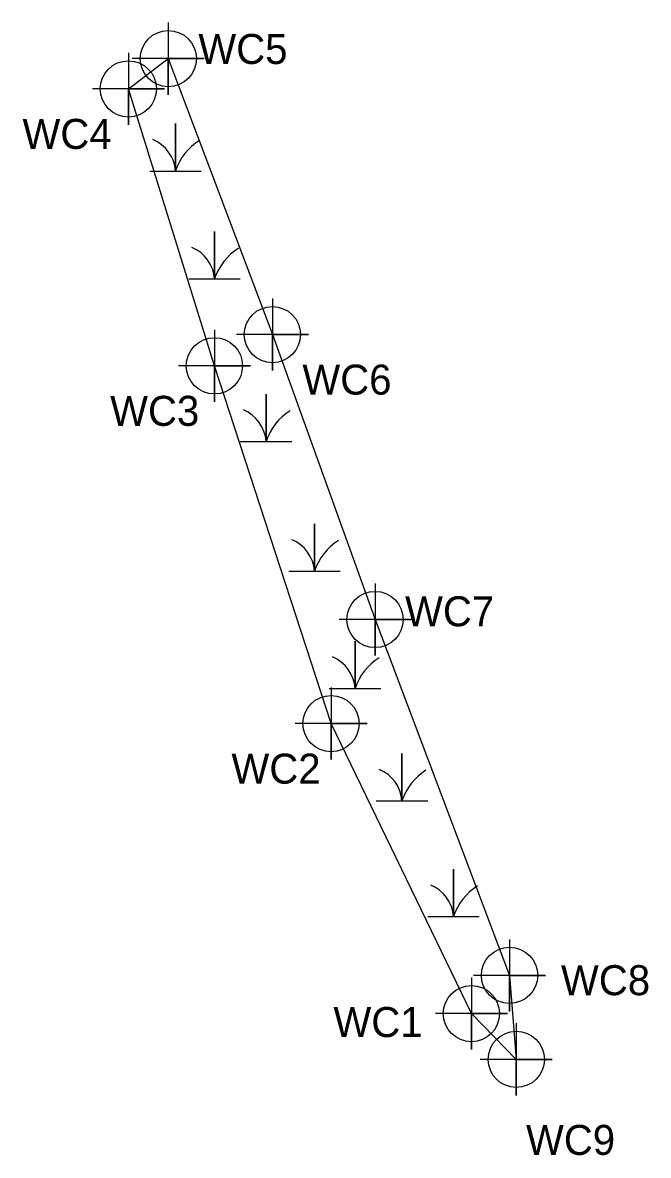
# Model space of a CAD drawing. Extents: x 2603618 to 2605510, y 618189 to 619022.
# Drawn here: x 2603693.4 to 2603745.5, y 618592.9 to 618687.3 of the extents above; entities that cross this region are included whole.
import ezdxf

# ---------------------------------------------------------------- set-up
doc = ezdxf.new("R2010")
doc.units = 0
for name, color, linetype in [('Exist Environmental Wetland Boundary', 7, 'Continuous'), ('Exist Environmental Wetland Boundary Cogo Comment', 7, 'Continuous'), ('Exist Environmental Wetland Boundary Cogo Point CELL', 7, 'Continuous'), ('Exist Hydro Swamp or Marsh', 7, 'Continuous')]:
    doc.layers.add(name, color=color, linetype=linetype)

# ---------------------------------------------------------------- blocks, each defined once
blk = doc.blocks.new('Exist Hydro Swamp or Marsh')
at = {"layer": 'Exist Hydro Swamp or Marsh'}
blk.add_line((0, 0), (0, 0), dxfattribs=at)
blk.add_lwpolyline([(-0.043, -0.0357), (0, -0.0357), (0, 0.0432), (0, -0.0357), (0.043, -0.0357)], dxfattribs=at)
for centre, radius, start, end in [((-0.0613, -0.0401), 0.0615, 4.1403, 67.535), ((0.0912, -0.066), 0.0961, 122.1274, 161.6222)]:
    blk.add_arc(centre, radius, start, end, dxfattribs=at)

msp = doc.modelspace()

# ---------------------------------------------------------------- linework, layer by layer
at = {"layer": 'Exist Environmental Wetland Boundary'}
msp.add_line((2603730.792, 618604.745), (2603734.534, 618600.938), dxfattribs=at)
msp.add_lwpolyline([(2603730.792, 618604.745), (2603719.096, 618628.908), (2603709.376, 618658.718), (2603702.202, 618681.791), (2603705.534, 618684.31), (2603714.205, 618661.32), (2603722.762, 618637.586), (2603733.971, 618607.934), (2603734.534, 618600.938)], dxfattribs=at)
at = {"layer": 'Exist Environmental Wetland Boundary Cogo Point CELL'}
for points in [[(2603705.534, 618687.31), (2603705.534, 618681.31), (2603705.534, 618684.31), (2603708.534, 618684.31), (2603702.534, 618684.31)], [(2603702.202, 618684.791), (2603702.202, 618678.791), (2603702.202, 618681.791), (2603705.202, 618681.791), (2603699.202, 618681.791)], [(2603714.205, 618664.32), (2603714.205, 618658.32), (2603714.205, 618661.32), (2603717.205, 618661.32), (2603711.205, 618661.32)], [(2603709.376, 618661.718), (2603709.376, 618655.718), (2603709.376, 618658.718), (2603712.376, 618658.718), (2603706.376, 618658.718)], [(2603722.762, 618640.586), (2603722.762, 618634.586), (2603722.762, 618637.586), (2603725.762, 618637.586), (2603719.762, 618637.586)], [(2603719.096, 618631.908), (2603719.096, 618625.908), (2603719.096, 618628.908), (2603722.096, 618628.908), (2603716.096, 618628.908)], [(2603733.971, 618610.934), (2603733.971, 618604.934), (2603733.971, 618607.934), (2603736.971, 618607.934), (2603730.971, 618607.934)], [(2603730.792, 618607.745), (2603730.792, 618601.745), (2603730.792, 618604.745), (2603733.792, 618604.745), (2603727.792, 618604.745)], [(2603734.534, 618603.938), (2603734.534, 618597.938), (2603734.534, 618600.938), (2603737.534, 618600.938), (2603731.534, 618600.938)]]:
    msp.add_lwpolyline(points, dxfattribs=at)
for centre in [(2603705.534, 618684.31), (2603702.202, 618681.791), (2603714.205, 618661.32), (2603709.376, 618658.718), (2603722.762, 618637.586), (2603719.096, 618628.908), (2603733.971, 618607.934), (2603730.792, 618604.745), (2603734.534, 618600.938)]:
    msp.add_circle(centre, 2.344, dxfattribs=at)

# ---------------------------------------------------------------- block references
at = {"layer": 'Exist Hydro Swamp or Marsh', "xscale": 50, "yscale": 50}
for p in [(2603706.13, 618676.735), (2603709.384, 618667.749), (2603713.68, 618654.206), (2603717.714, 618643.397), (2603721.099, 618633.63), (2603725.003, 618624.254), (2603729.299, 618614.618)]:
    msp.add_blockref('Exist Hydro Swamp or Marsh', p, dxfattribs=at)

# ---------------------------------------------------------------- texts
at = {"layer": 'Exist Environmental Wetland Boundary Cogo Comment'}
for s, p in [('WC5', (2603708.034, 618683.868)), ('WC4', (2603693.378, 618676.791)), ('WC6', (2603716.705, 618656.32)), ('WC3', (2603700.682, 618653.718)), ('WC7', (2603725.262, 618637.014)), ('WC2', (2603710.793, 618623.908)), ('WC8', (2603738.256, 618606.283)), ('WC1', (2603719.294, 618602.796)), ('WC9', (2603735.342, 618592.975))]:
    msp.add_text(s, height=2.5, dxfattribs=at).set_placement(p)

doc.saveas('drawing.dxf')
